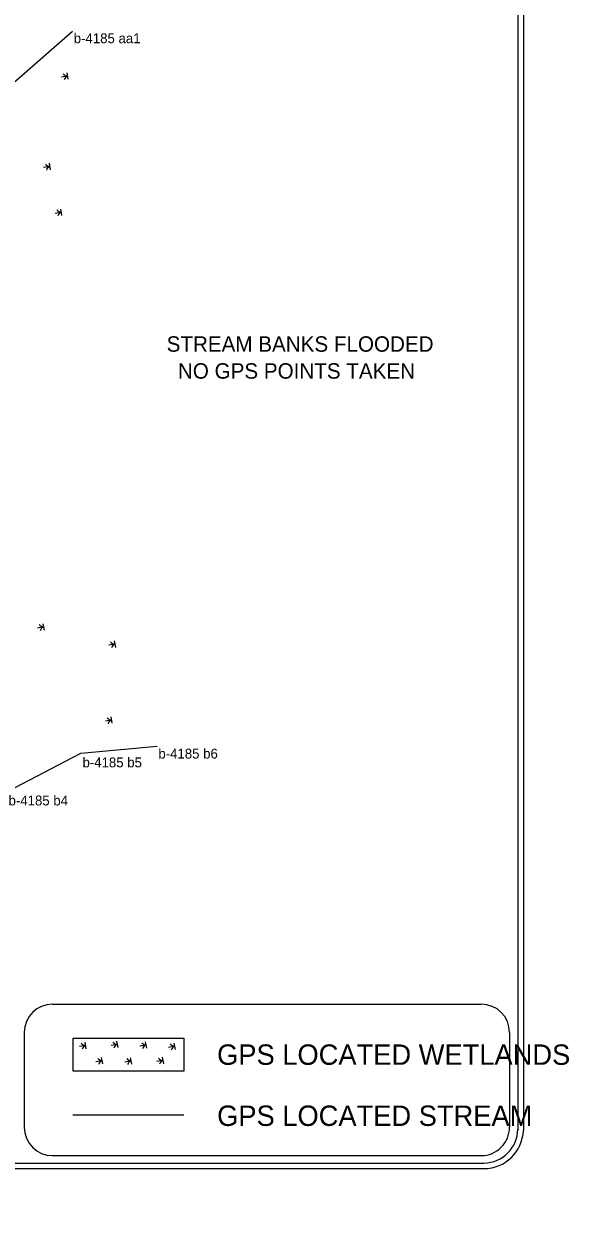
# Model space of a CAD drawing. Extents: x 2598976 to 2600165, y 728604 to 730243.
# Drawn here: x 2599645 to 2600059, y 728604 to 729516 of the extents above; entities that cross this region are included whole.
import ezdxf

# ---------------------------------------------------------------- set-up
doc = ezdxf.new("R2010")
doc.units = 0
for name, color, linetype in [('Old_Level_24', 7, 'Continuous'), ('Old_Level_3', 7, 'Continuous'), ('Old_Level_57', 7, 'Continuous'), ('Old_Level_63', 7, 'Continuous')]:
    doc.layers.add(name, color=color, linetype=linetype)

msp = doc.modelspace()

# ---------------------------------------------------------------- linework, layer by layer
at = {"layer": 'Old_Level_3'}
for p, q in [((2599681.53, 729510.24), (2599681.53, 729510.24)), ((2599687.87, 728961.4), (2599687.87, 728961.4)), ((2599745.82, 728966.7), (2599745.82, 728966.7))]:
    msp.add_line(p, q, dxfattribs=at)
at = {"layer": 'Old_Level_57'}
for p, q in [((2599677.8, 729476.28), (2599673.01, 729475.42)), ((2599678.24, 729473.82), (2599677.36, 729478.74)), ((2599664.26, 729407.57), (2599659.47, 729406.71)), ((2599664.7, 729405.11), (2599663.82, 729410.03)), ((2599672.96, 729372.73), (2599668.17, 729371.88)), ((2599673.4, 729370.27), (2599672.52, 729375.19)), ((2599659.64, 729057.43), (2599654.85, 729056.58)), ((2599660.07, 729054.97), (2599659.2, 729059.89)), ((2599713.82, 729044.32), (2599709.03, 729043.46)), ((2599714.26, 729041.85), (2599713.38, 729046.78)), ((2599711.64, 728984.15), (2599710.76, 728989.07)), ((2599711.2, 728986.61), (2599706.41, 728985.76))]:
    msp.add_line(p, q, dxfattribs=at)
for points in [[(2599681.53, 729510.24), (2599547.27, 729393.05), (2599518.57, 729299.5)], [(2599516.89, 729220.46), (2599540.31, 728994.01), (2599562.39, 728942.84), (2599631.97, 728932.34), (2599687.87, 728961.4), (2599745.82, 728966.7)]]:
    msp.add_lwpolyline(points, dxfattribs=at)
for centre, radius, start, end in [((2599678.27, 729481.41), 5.15, 220.90031, 264.24799), ((2599678.85, 729472.52), 3.87, 105.65345, 165.99432), ((2599664.72, 729412.7), 5.15, 220.90031, 264.24799), ((2599665.3, 729403.81), 3.87, 105.65345, 165.99432), ((2599673.43, 729377.86), 5.15, 220.90031, 264.24799), ((2599674.01, 729368.98), 3.87, 105.65345, 165.99432), ((2599660.1, 729062.56), 5.15, 220.90031, 264.24799), ((2599660.68, 729053.68), 3.87, 105.65345, 165.99432), ((2599714.29, 729049.45), 5.15, 220.90031, 264.24799), ((2599714.87, 729040.56), 3.87, 105.65345, 165.99432), ((2599711.67, 728991.75), 5.15, 220.90031, 264.24799), ((2599712.25, 728982.86), 3.87, 105.65345, 165.99432)]:
    msp.add_arc(centre, radius, start, end, dxfattribs=at)
at = {"layer": 'Old_Level_63'}
for p, q in [((2600019.84, 730208.54), (2600019.84, 728674.58)), ((2600019.84, 730208.54), (2600019.84, 728674.58)), ((2600019.84, 730208.54), (2600019.84, 728674.58)), ((2600024.14, 730208.54), (2600024.14, 728674.53)), ((2600024.14, 730208.54), (2600024.14, 728674.53)), ((2600024.14, 730208.54), (2600024.14, 728674.53)), ((2599666.26, 728770.62), (2599992.13, 728770.62)), ((2599644.76, 728749.11), (2599644.76, 728676.99)), ((2599691.92, 728736.75), (2599691.04, 728741.67)), ((2599716.02, 728737.54), (2599715.14, 728742.46)), ((2599737.9, 728737.06), (2599737.02, 728741.99)), ((2600013.64, 728749.11), (2600013.64, 728677.01)), ((2599691.48, 728739.21), (2599686.69, 728738.35)), ((2599715.58, 728740), (2599710.79, 728739.15)), ((2599737.46, 728739.52), (2599732.67, 728738.67)), ((2599759.18, 728738.57), (2599754.39, 728737.72)), ((2599759.62, 728736.11), (2599758.74, 728741.03)), ((2599704.01, 728727.63), (2599699.22, 728726.78)), ((2599704.44, 728725.17), (2599703.57, 728730.09)), ((2599726.04, 728727.47), (2599721.25, 728726.62)), ((2599726.48, 728725.01), (2599725.6, 728729.93)), ((2599750.3, 728727.79), (2599745.51, 728726.93)), ((2599750.74, 728725.33), (2599749.86, 728730.25)), ((2599681.64, 728686.51), (2599766.05, 728686.51)), ((2599666.27, 728655.48), (2599992.14, 728655.48)), ((2599666.27, 728655.48), (2599992.14, 728655.48)), ((2599666.27, 728655.48), (2599992.14, 728655.48)), ((2599010.83, 728649.84), (2599994.19, 728649.84)), ((2599010.83, 728649.84), (2599994.19, 728649.84)), ((2599010.83, 728649.84), (2599994.19, 728649.84)), ((2599010.83, 728645.54), (2599994.19, 728645.54)), ((2599010.83, 728645.54), (2599994.19, 728645.54)), ((2599010.83, 728645.54), (2599994.19, 728645.54)), ((2599994.19, 728645.54), (2599994.22, 728645.54)), ((2599994.19, 728645.54), (2599994.22, 728645.54)), ((2599994.19, 728645.54), (2599994.22, 728645.54)), ((2600025.86, 728604.21), (2600025.86, 728604.21))]:
    msp.add_line(p, q, dxfattribs=at)
msp.add_lwpolyline([(2599681.89, 728744.72), (2599766, 728744.72), (2599766, 728719.75), (2599681.89, 728719.75)], close=True, dxfattribs=at)
for centre, radius, start, end in [((2599716.05, 728745.13), 5.15, 220.90031, 264.24799), ((2599737.92, 728744.66), 5.15, 220.90031, 264.24799), ((2599691.95, 728744.34), 5.15, 220.90031, 264.24799), ((2599692.53, 728735.45), 3.87, 105.65345, 165.99432), ((2599716.63, 728736.25), 3.87, 105.65345, 165.99432), ((2599738.51, 728735.77), 3.87, 105.65345, 165.99432), ((2599759.64, 728743.71), 5.15, 220.90031, 264.24799), ((2599760.23, 728734.82), 3.87, 105.65345, 165.99432), ((2599704.47, 728732.76), 5.15, 220.90031, 264.24799), ((2599705.05, 728723.88), 3.87, 105.65345, 165.99432), ((2599726.51, 728732.6), 5.15, 220.90031, 264.24799), ((2599727.09, 728723.72), 3.87, 105.65345, 165.99432), ((2599750.77, 728732.92), 5.15, 220.90031, 264.24799), ((2599751.35, 728724.03), 3.87, 105.65345, 165.99432)]:
    msp.add_arc(centre, radius, start, end, dxfattribs=at)
for centre, major_axis, ratio, start_param, end_param in [((2599666.26, 728749.11), (0, -21.51), 0.999998, 3.141593, 4.712389), ((2599992.13, 728749.11), (0, 21.51), 0.999998, 4.712389, 6.283185), ((2599666.27, 728676.99), (0, -21.51), 0.999998, 4.712389, 6.283185), ((2599666.27, 728676.99), (0, -21.51), 0.999998, 4.712389, 6.283185), ((2599666.27, 728676.99), (0, -21.51), 0.999998, 4.712389, 6.283185), ((2599992.1, 728677.01), (0, 21.53), 0.999998, 3.141591, 4.712389), ((2599992.1, 728677.01), (0, 21.53), 0.999998, 3.141591, 4.712389), ((2599992.1, 728677.01), (0, 21.53), 0.999998, 3.141591, 4.712389), ((2599994.03, 728675.68), (25.84, 0), 0.999998, 4.718762, 6.282207), ((2599994.03, 728675.68), (25.84, 0), 0.999998, 4.718762, 6.282207), ((2599994.03, 728675.68), (25.84, 0), 0.999998, 4.718762, 6.282207), ((2599994.03, 728675.68), (30.14, 0), 0.999993, 4.718762, 6.244803), ((2599994.03, 728675.68), (30.14, 0), 0.999993, 4.718762, 6.244803), ((2599994.03, 728675.68), (30.14, 0), 0.999993, 4.718762, 6.244803)]:
    msp.add_ellipse(centre, major_axis=major_axis, ratio=ratio, start_param=start_param, end_param=end_param, dxfattribs=at)

# ---------------------------------------------------------------- texts
at = {"layer": 'Old_Level_24'}
for s, height, p in [('b-4185 aa1', 7.5, (2599682.38, 729501.27)), ('STREAM BANKS FLOODED', 11.7188, (2599752.98, 729266.69)), ('NO GPS POINTS TAKEN', 11.7188, (2599761.57, 729246.21)), ('b-4185 b6', 7.5, (2599746.71, 728957.35)), ('b-4185 b5', 7.5, (2599689.04, 728950.67)), ('b-4185 b4', 7.5, (2599632.84, 728921.72))]:
    msp.add_text(s, height=height, dxfattribs=at).set_placement(p)
at = {"layer": 'Old_Level_63'}
for s, p in [('GPS LOCATED WETLANDS', (2599791.34, 728724.49)), ('GPS LOCATED STREAM', (2599791.34, 728678.03))]:
    msp.add_text(s, height=15.5052, dxfattribs=at).set_placement(p)

doc.saveas('drawing.dxf')
